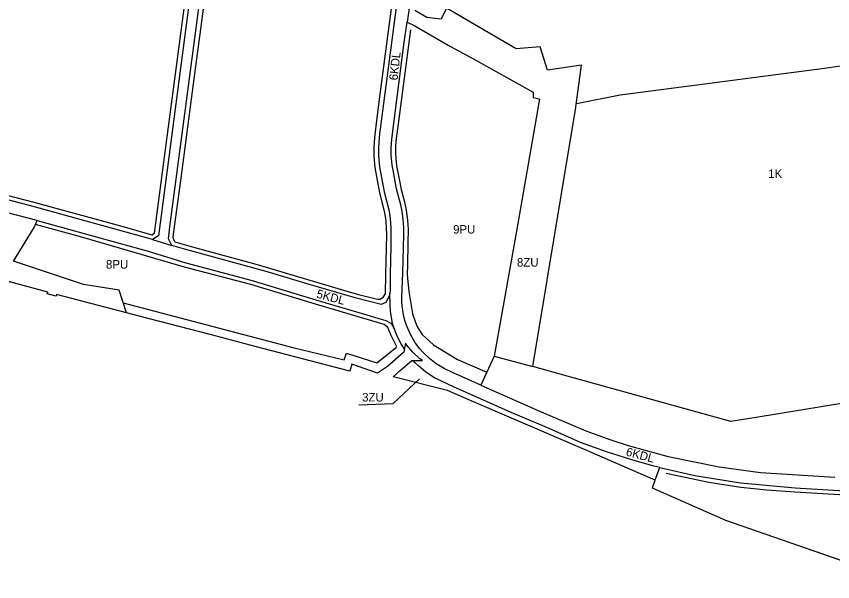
# Model space of a CAD drawing. Extents: x 7428203 to 7432868, y 5542672 to 5545406.
# Drawn here: x 7428940 to 7429895, y 5543758 to 5544419 of the extents above; entities that cross this region are included whole.
import ezdxf

# ---------------------------------------------------------------- set-up
doc = ezdxf.new("R2010")
doc.units = 0
for name, color, linetype in [('granica_planu', 7, 'Continuous'), ('linie_rozgraniczajace', 7, 'Continuous'), ('linie_zabudowy_nieprzekraczalne', 7, 'Continuous'), ('oznaczenia_przeznaczen', 7, 'Continuous')]:
    doc.layers.add(name, color=color, linetype=linetype)

msp = doc.modelspace()

# ---------------------------------------------------------------- linework, layer by layer
at = {"layer": 'granica_planu'}
msp.add_lwpolyline([(7429976.28, 5543757.53), (7429864.43, 5543796.42), (7429769.93, 5543829.29), (7429684, 5543866.99), (7429684.97, 5543869.82), (7429687.25, 5543876.37), (7429670.15, 5543883.75), (7429622.53, 5543904.3), (7429604.6, 5543912.04), (7429521.96, 5543947.71), (7429474.6, 5543968.15), (7429444.36, 5543981.21), (7429380.81, 5543997.1), (7429389.04, 5544004.48), (7429402.37, 5544016.42), (7429414.91, 5544016.13), (7429412.05, 5544018.34), (7429403.87, 5544025.95), (7429396.19, 5544034.81), (7429395, 5544036.69), (7429393.34, 5544026.23), (7429374.21, 5544009.14), (7429362.52, 5544001.5), (7429332.52, 5544011.99), (7429330.2, 5544003.84), (7429219.11, 5544032.89), (7429166.46, 5544046.67), (7429083.71, 5544068.31), (7429068.86, 5544072.19), (7428986.99, 5544093.6), (7428986.46, 5544091.47), (7428976.04, 5544094.28), (7428976.57, 5544096.41), (7428860.8, 5544127.52)], dxfattribs=at)
at = {"layer": 'linie_rozgraniczajace'}
for p, q in [((7429099.14, 5544157.86), (7429121.95, 5544150.94)), ((7428976.57, 5544096.41), (7428860.8, 5544127.52)), ((7428976.04, 5544094.28), (7428976.57, 5544096.41)), ((7428986.46, 5544091.47), (7428976.04, 5544094.28)), ((7428986.99, 5544093.6), (7428986.46, 5544091.47)), ((7429068.86, 5544072.19), (7428986.99, 5544093.6)), ((7429083.71, 5544068.31), (7429068.86, 5544072.19)), ((7429166.46, 5544046.67), (7429083.71, 5544068.31)), ((7429219.11, 5544032.89), (7429166.46, 5544046.67)), ((7429395, 5544036.69), (7429393.34, 5544026.23)), ((7429396.19, 5544034.81), (7429395, 5544036.69)), ((7429330.2, 5544003.84), (7429219.11, 5544032.89)), ((7429403.87, 5544025.95), (7429396.19, 5544034.81)), ((7429393.34, 5544026.23), (7429374.21, 5544009.14)), ((7429412.05, 5544018.34), (7429403.87, 5544025.95)), ((7429414.91, 5544016.13), (7429412.05, 5544018.34)), ((7429332.52, 5544011.99), (7429330.2, 5544003.84)), ((7429362.52, 5544001.5), (7429332.52, 5544011.99)), ((7429374.21, 5544009.14), (7429362.52, 5544001.5)), ((7429389.04, 5544004.48), (7429402.37, 5544016.42)), ((7429402.37, 5544016.42), (7429414.91, 5544016.13)), ((7429380.81, 5543997.1), (7429389.04, 5544004.48)), ((7429444.36, 5543981.21), (7429380.81, 5543997.1)), ((7429474.6, 5543968.15), (7429444.36, 5543981.21)), ((7429521.96, 5543947.71), (7429474.6, 5543968.15)), ((7429604.6, 5543912.04), (7429521.96, 5543947.71)), ((7429622.53, 5543904.3), (7429604.6, 5543912.04)), ((7429670.15, 5543883.75), (7429622.53, 5543904.3)), ((7429687.25, 5543876.37), (7429670.15, 5543883.75)), ((7429684.97, 5543869.82), (7429687.25, 5543876.37)), ((7429684, 5543866.99), (7429684.97, 5543869.82)), ((7429769.93, 5543829.29), (7429684, 5543866.99)), ((7429864.43, 5543796.42), (7429769.93, 5543829.29)), ((7429976.28, 5543757.53), (7429864.43, 5543796.42))]:
    msp.add_line(p, q, dxfattribs=at)
for points in [[(7429198.67, 5544727.47), (7429176.49, 5544739.59), (7429181.27, 5544730.14), (7429139.09, 5544411.72), (7429106.05, 5544162.35), (7429099.14, 5544157.86), (7428955.29, 5544197.85), (7428805.14, 5544236.81), (7428800.36, 5544244.12), (7428835.48, 5544505.35), (7428871.87, 5544782.58), (7428886.98, 5544894.27), (7428893.15, 5544897.22), (7428979.15, 5544848.51), (7428994.76, 5544839.83), (7428990.64, 5544827.77), (7428982.93, 5544761.65), (7428979.22, 5544729.83), (7429033.78, 5544721.61), (7429045.31, 5544798.17), (7429047.66, 5544810.44), (7429085.54, 5544789.39), (7429155.84, 5544750.87), (7429176.49, 5544739.59)], [(7428964.08, 5544180.06), (7429037.36, 5544159.85), (7429094.05, 5544144.08), (7429138.08, 5544130.52), (7429215.73, 5544110.08), (7429295.33, 5544085.88), (7429354, 5544068.58), (7429364.09, 5544065.6), (7429371.99, 5544063.24), (7429378.01, 5544060.16), (7429381.22, 5544055.34), (7429381.99, 5544053.37), (7429381.64, 5544054.57), (7429379.86, 5544059.92), (7429377.73, 5544073.72), (7429377.26, 5544081.59), (7429376.71, 5544095.24), (7429375.93, 5544091.53), (7429372.24, 5544084.33), (7429366.79, 5544081.9), (7429336.24, 5544089.46), (7429281.08, 5544105.73), (7429232.22, 5544120.6), (7429137.95, 5544146.09), (7429121.95, 5544150.94), (7429117.72, 5544158.72), (7429119.57, 5544172.92), (7429137.15, 5544304.86), (7429192.3, 5544724.11)], [(7429389.85, 5544471.47), (7429364.8, 5544281.38), (7429364.17, 5544276.36), (7429363.43, 5544265.84), (7429363.45, 5544255.69), (7429364.63, 5544242.97), (7429370.15, 5544213.76), (7429375.88, 5544191.22), (7429377.31, 5544181.97), (7429378.07, 5544171.5), (7429378.15, 5544163.57), (7429377.9, 5544149.97), (7429377.05, 5544117.07), (7429377.29, 5544097.94), (7429376.71, 5544095.24)], [(7429399.4, 5544428.49), (7429397.26, 5544412.31), (7429406.02, 5544407.99), (7429447.97, 5544383.8), (7429473.2, 5544370.15), (7429544.5, 5544330.23), (7429544.47, 5544323.93), (7429551.8, 5544322.49), (7429549.72, 5544308.79), (7429525.07, 5544167.56), (7429498.93, 5544021.41), (7429543.98, 5544009.32), (7429594.13, 5544310.09), (7429600.95, 5544361.82), (7429561.15, 5544356.18), (7429552.57, 5544383.46), (7429524.5, 5544381.03), (7429443.24, 5544428.41), (7429436.74, 5544415.56), (7429420.03, 5544417.78), (7429406.07, 5544425.77)], [(7429498.93, 5544021.41), (7429483.45, 5543987.53), (7429450.08, 5544002.33), (7429440.43, 5544006.83), (7429430.98, 5544012.53), (7429423.1, 5544018.6), (7429415.44, 5544025.99), (7429411.66, 5544030.34), (7429406.17, 5544037.82), (7429401.02, 5544046.66), (7429396.97, 5544055.78), (7429394.86, 5544061.96), (7429392.96, 5544069.31), (7429391.91, 5544075.12), (7429391.32, 5544079.85), (7429390.94, 5544085.76), (7429390.91, 5544090.5), (7429392.09, 5544118.74), (7429393.15, 5544163.51), (7429393.06, 5544172.05), (7429392.42, 5544181.2), (7429391.14, 5544190.91), (7429389.68, 5544198.36), (7429384.8, 5544217.01), (7429380.98, 5544237.19), (7429379.5, 5544245.06), (7429378.45, 5544256.39), (7429378.43, 5544265.32), (7429379.14, 5544275.25), (7429393.58, 5544388.64), (7429397.26, 5544412.31)], [(7429068.86, 5544072.19), (7429060.22, 5544098.67), (7429018.58, 5544105.27), (7428936.65, 5544132.38), (7428960.84, 5544171.8), (7428964.08, 5544180.06), (7428802.22, 5544221.94), (7428661.3, 5544258.99), (7428659.05, 5544253.72), (7428653.94, 5544238.67), (7428649.37, 5544214.38), (7428584.29, 5544238.12)], [(7429381.99, 5544053.37), (7429384.4, 5544047.27), (7429387.4, 5544040.36), (7429390.58, 5544034.5), (7429393.83, 5544029.35)], [(7429686.91, 5543876.52), (7429687.33, 5543876.59), (7429692.68, 5543891.06), (7429685.7, 5543892.8), (7429660.05, 5543899.99), (7429630.15, 5543909.54), (7429599.89, 5543920.53), (7429563.13, 5543936.87), (7429521.33, 5543954.32), (7429452, 5543985.07), (7429428.41, 5543996.37), (7429418.44, 5544003.09), (7429410.74, 5544009.52), (7429406.52, 5544013.6), (7429403.94, 5544016.38)], [(7429959.79, 5543974.93), (7429805.3, 5543949.82), (7429775.88, 5543945.04), (7429585.97, 5543997.5), (7429543.98, 5544009.32)], [(7429483.45, 5543987.53), (7429551.2, 5543957.47), (7429606.21, 5543934.17), (7429635.3, 5543923.63), (7429655.65, 5543917), (7429702.65, 5543903.98), (7429762.19, 5543891.88), (7429810.29, 5543885.43), (7429897.37, 5543879.68)], [(7429692.68, 5543891.06), (7429733.68, 5543881.76), (7429787.12, 5543873.02), (7429851.1, 5543867.29), (7429960.09, 5543860.73), (7429984.9, 5543859.31), (7430010.49, 5543857.85), (7430047.45, 5543855.75), (7430162.05, 5543849.26), (7430213.06, 5543846.63), (7430226.75, 5543846.71), (7430245.5, 5543848.19), (7430288.91, 5543854.44), (7430330.3, 5543860.39), (7430346.69, 5543847.34), (7430344.79, 5543892.69)]]:
    msp.add_lwpolyline(points, dxfattribs=at)
at = {"layer": 'linie_zabudowy_nieprzekraczalne'}
for p, q in [((7429885.23, 5544358.31), (7430101.92, 5544389.47)), ((7429646.41, 5544327.23), (7429885.23, 5544358.31)), ((7429595.21, 5544316.97), (7429646.41, 5544327.23))]:
    msp.add_line(p, q, dxfattribs=at)
msp.add_lwpolyline([(7428892.96, 5544891.59), (7428891.57, 5544890.93), (7428873.42, 5544756.02), (7428838.05, 5544486.51), (7428824.47, 5544383), (7428809.45, 5544270.11), (7428805.6, 5544245.24), (7428808.27, 5544241.17), (7428960.48, 5544201.62), (7429063.14, 5544173.58), (7429098.37, 5544163.32), (7429101.4, 5544165.29), (7429115.21, 5544269.13), (7429156.74, 5544584.47), (7429176.11, 5544729.27), (7429172.73, 5544735.95), (7429073.35, 5544790.45), (7428930.42, 5544870.37)], close=True, dxfattribs=at)
for points in [[(7429168.34, 5544502.96), (7429155.31, 5544403.82), (7429150.66, 5544369.28), (7429145.62, 5544330.94), (7429132.18, 5544229.57), (7429123.49, 5544164.28), (7429122.89, 5544159.69), (7429125.37, 5544155.13), (7429147.04, 5544148.85), (7429221.64, 5544128.64), (7429322.76, 5544098.64), (7429340.1, 5544093.62), (7429360.86, 5544088.3), (7429363.27, 5544087.93), (7429365.85, 5544088.17), (7429366.46, 5544088.37), (7429369.41, 5544090.85), (7429371.73, 5544094.28), (7429372.05, 5544117.11), (7429373.15, 5544163.59), (7429373.07, 5544171.31), (7429372.48, 5544179.62), (7429371.09, 5544189.69), (7429365.26, 5544212.68), (7429359.67, 5544242.27), (7429358.45, 5544255.45), (7429358.43, 5544266.01), (7429359.18, 5544276.71), (7429360.89, 5544290.44), (7429364.86, 5544322.25), (7429402.06, 5544605.4)], [(7429400.91, 5544403.19), (7429386.79, 5544295.83), (7429383.99, 5544272.97), (7429383.45, 5544265.36), (7429383.44, 5544259.2), (7429383.78, 5544253.07), (7429384.26, 5544247.81), (7429385.12, 5544242.24), (7429387.68, 5544228.66), (7429390.09, 5544216.48), (7429393.79, 5544201.97), (7429395.97, 5544192.35), (7429397.49, 5544180.5), (7429398.08, 5544169.66), (7429397.98, 5544154.03), (7429397.33, 5544127.64), (7429397.08, 5544117.76), (7429397.65, 5544112.16), (7429399.23, 5544096.94), (7429402.97, 5544073.48), (7429403.4, 5544070.83), (7429405.87, 5544063.23), (7429407.69, 5544058.67), (7429409.61, 5544054.72), (7429414.66, 5544046.86), (7429427.93, 5544034.62), (7429455.8, 5544017.45), (7429490.35, 5544002.62)], [(7429384.93, 5544032.13), (7429378.37, 5544045.55), (7429374.6, 5544054.83), (7429370.29, 5544058.53), (7429362.37, 5544060.9), (7429293.91, 5544081.08), (7429214.36, 5544105.27), (7429136.7, 5544125.71), (7429016.65, 5544160.8), (7428962.24, 5544175.37)], [(7429064.63, 5544083.66), (7429264.77, 5544031.29), (7429323.55, 5544017.01), (7429326.07, 5544024.84), (7429361.69, 5544013.62), (7429384.81, 5544032.03)], [(7430352.56, 5543805.37), (7430345.56, 5543820.39), (7430342.81, 5543831.42), (7430341.79, 5543844.85), (7430328.95, 5543855.08), (7430246.14, 5543843.23), (7430226.91, 5543841.71), (7430212.94, 5543841.63), (7430161.78, 5543844.27), (7430047.23, 5543850.54), (7429850.78, 5543862.3), (7429817.78, 5543864.62), (7429787.47, 5543867.62), (7429750.04, 5543873.61), (7429700.15, 5543884.05)]]:
    msp.add_lwpolyline(points, dxfattribs=at)
at = {"layer": 'oznaczenia_przeznaczen'}
msp.add_lwpolyline([(7429340.5, 5543964.36), (7429380.55, 5543965.98), (7429411.59, 5543995.04)], dxfattribs=at)

# ---------------------------------------------------------------- texts
for s, rotation, p in [('6KDL', 83.6446752, (7429385.8022, 5544343.752)), ('5KDL', 345.0952611, (7429290.3202, 5544090.0027)), ('6KDL', 345.0952611, (7429652.3702, 5543905.2327))]:
    msp.add_text(s, height=10, rotation=rotation, dxfattribs=at).set_placement(p)
for s, p in [('1K', (7429819.524, 5544229.98)), ('9PU', (7429450.8459, 5544164.8)), ('8PU', (7429044.7059, 5544123.83)), ('8ZU', (7429525.4959, 5544126.16)), ('3ZU', (7429344.4059, 5543968.36))]:
    msp.add_text(s, height=10, dxfattribs=at).set_placement(p)

doc.saveas('drawing.dxf')
